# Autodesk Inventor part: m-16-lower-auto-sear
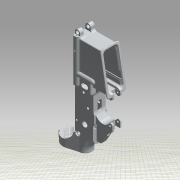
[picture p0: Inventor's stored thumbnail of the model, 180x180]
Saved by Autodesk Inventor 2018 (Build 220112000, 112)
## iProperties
Created: 2019-01
Part Number: m-16-lower-auto-sear
Material: Generic
Description: XXXXXXXXXXXXXXXXXXXXXXXXXXXXXXXXXXXXXXXXXXXXXXXXXXXXXXXXXXXXXXX
Document SubType Name: Modeling
Designer: johne
Appearance: Default
Sending System: Autodesk Inventor 2018
Preprocessor: ST-DEVELOPER v16.13
Title: D:\Downloads\AP9 Shit\m-16-lower-auto-sear.stp
Author: johne
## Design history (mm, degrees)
feature "Solid1"
body "Solid2"
